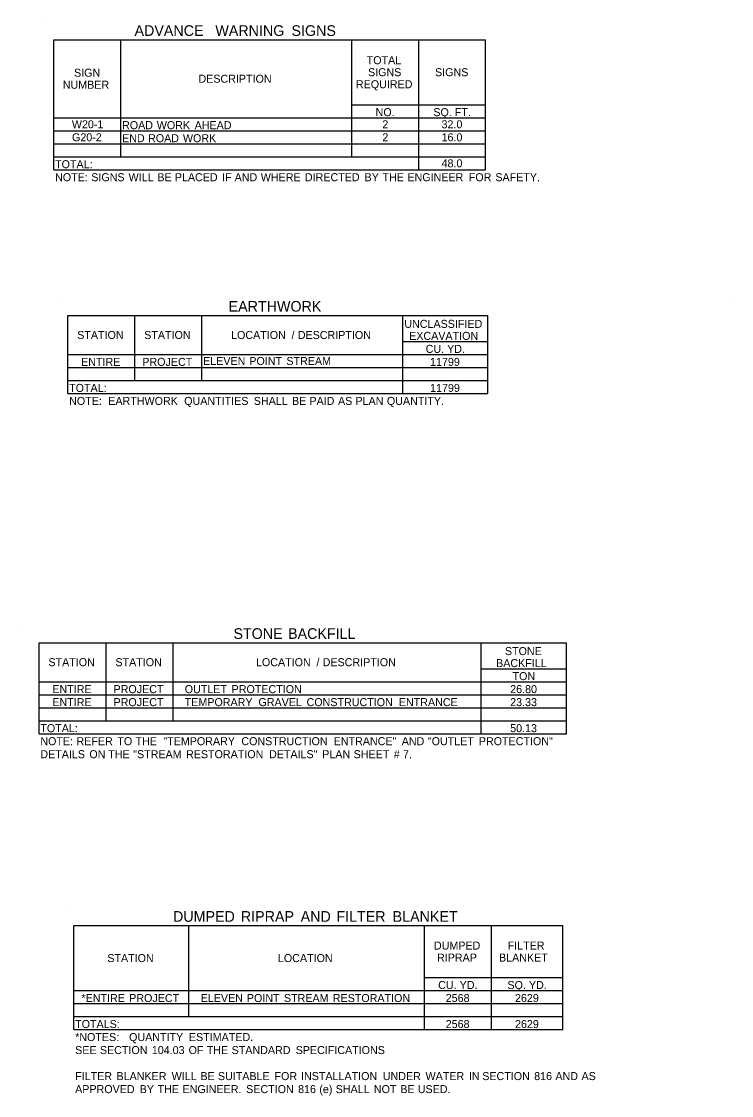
# Model space of a CAD drawing. Extents: x -2001791 to 62654501, y -2521700 to -592476.
# Drawn here: x -2001791 to -2001259, y -593387 to -592582 of the extents above; entities that cross this region are included whole.
import ezdxf

# ---------------------------------------------------------------- set-up
doc = ezdxf.new("R2010")
doc.units = 0
doc.layers.add('Default', color=7, linetype='Continuous')
doc.layers.add('R_Border', color=7, linetype='Continuous')

msp = doc.modelspace()

# ---------------------------------------------------------------- linework, layer by layer
at = {"layer": 'Default'}
for p, q in [((-2001767.25, -592596.02), (-2001443.55, -592596.02)), ((-2001767.25, -592693.52), (-2001767.25, -592596.02)), ((-2001767.25, -592693.52), (-2001767.25, -592596.02)), ((-2001717.04, -592683.77), (-2001717.04, -592596.02)), ((-2001543.98, -592683.77), (-2001543.98, -592596.02)), ((-2001493.76, -592644.77), (-2001493.76, -592596.02)), ((-2001493.76, -592693.52), (-2001493.76, -592596.02)), ((-2001443.55, -592693.52), (-2001443.55, -592596.02)), ((-2001443.55, -592693.52), (-2001443.55, -592596.02)), ((-2001543.98, -592644.77), (-2001443.55, -592644.77)), ((-2001767.25, -592654.52), (-2001443.55, -592654.52)), ((-2001717.04, -592683.77), (-2001717.04, -592654.52)), ((-2001543.98, -592683.77), (-2001543.98, -592654.52)), ((-2001493.76, -592693.52), (-2001493.76, -592654.52)), ((-2001767.25, -592664.27), (-2001443.55, -592664.27)), ((-2001767.25, -592674.02), (-2001443.55, -592674.02)), ((-2001543.98, -592674.02), (-2001443.55, -592674.02)), ((-2001767.25, -592683.77), (-2001543.98, -592683.77)), ((-2001767.25, -592683.77), (-2001443.55, -592683.77)), ((-2001767.25, -592693.52), (-2001443.55, -592693.52)), ((-2001756.73, -592802.65), (-2001441.81, -592802.65)), ((-2001756.73, -592861.15), (-2001756.73, -592802.65)), ((-2001756.73, -592861.15), (-2001756.73, -592802.65)), ((-2001706.52, -592851.4), (-2001706.52, -592802.65)), ((-2001656.31, -592851.4), (-2001656.31, -592802.65)), ((-2001505.67, -592861.15), (-2001505.67, -592802.65)), ((-2001441.81, -592822.15), (-2001441.81, -592802.65)), ((-2001441.81, -592861.15), (-2001441.81, -592802.65)), ((-2001505.67, -592822.15), (-2001441.81, -592822.15)), ((-2001441.81, -592831.9), (-2001441.81, -592822.15)), ((-2001756.73, -592831.9), (-2001441.81, -592831.9)), ((-2001756.73, -592831.9), (-2001441.81, -592831.9)), ((-2001706.52, -592851.4), (-2001706.52, -592831.9)), ((-2001656.31, -592851.4), (-2001656.31, -592831.9)), ((-2001505.67, -592851.4), (-2001505.67, -592831.9)), ((-2001441.81, -592861.15), (-2001441.81, -592831.9)), ((-2001756.73, -592841.65), (-2001441.81, -592841.65)), ((-2001756.73, -592851.4), (-2001706.52, -592851.4)), ((-2001756.73, -592851.4), (-2001441.81, -592851.4)), ((-2001756.73, -592861.15), (-2001441.81, -592861.15)), ((-2001778.31, -593047.86), (-2001382.94, -593047.86)), ((-2001778.31, -593116.11), (-2001778.31, -593047.86)), ((-2001778.31, -593116.11), (-2001778.31, -593047.86)), ((-2001728.09, -593106.36), (-2001728.09, -593047.86)), ((-2001677.88, -593106.36), (-2001677.88, -593047.86)), ((-2001446.81, -593116.11), (-2001446.81, -593047.86)), ((-2001382.94, -593116.11), (-2001382.94, -593047.86)), ((-2001382.94, -593116.11), (-2001382.94, -593047.86)), ((-2001446.81, -593067.36), (-2001382.94, -593067.36)), ((-2001778.31, -593077.11), (-2001382.94, -593077.11)), ((-2001728.09, -593106.36), (-2001728.09, -593077.11)), ((-2001677.88, -593106.36), (-2001677.88, -593077.11)), ((-2001446.81, -593106.36), (-2001446.81, -593077.11)), ((-2001778.31, -593086.86), (-2001382.94, -593086.86)), ((-2001728.09, -593086.86), (-2001677.88, -593086.86)), ((-2001778.31, -593096.61), (-2001382.94, -593096.61)), ((-2001778.31, -593106.36), (-2001382.94, -593106.36)), ((-2001778.31, -593106.36), (-2001382.94, -593106.36)), ((-2001778.31, -593116.11), (-2001382.94, -593116.11)), ((-2001752.22, -593259.83), (-2001385.62, -593259.83)), ((-2001752.22, -593337.83), (-2001752.22, -593259.83)), ((-2001752.22, -593337.83), (-2001752.22, -593259.83)), ((-2001665.93, -593328.08), (-2001665.93, -593259.83)), ((-2001489.46, -593337.83), (-2001489.46, -593259.83)), ((-2001439.24, -593337.83), (-2001439.24, -593259.83)), ((-2001385.62, -593337.83), (-2001385.62, -593259.83)), ((-2001385.62, -593337.83), (-2001385.62, -593259.83)), ((-2001489.46, -593298.83), (-2001385.62, -593298.83)), ((-2001752.22, -593308.58), (-2001385.62, -593308.58)), ((-2001752.22, -593308.58), (-2001385.62, -593308.58)), ((-2001665.93, -593328.08), (-2001665.93, -593308.58)), ((-2001489.46, -593337.83), (-2001489.46, -593308.58)), ((-2001752.22, -593318.33), (-2001385.62, -593318.33)), ((-2001752.22, -593328.08), (-2001665.93, -593328.08)), ((-2001752.22, -593328.08), (-2001385.62, -593328.08)), ((-2001752.22, -593337.83), (-2001385.62, -593337.83))]:
    msp.add_line(p, q, dxfattribs=at)
at = {"layer": 'R_Border'}
for p, q in [((-2001773.1, -592582.37), (-2001773.1, -592582.37)), ((-2001762.58, -592789), (-2001762.58, -592789)), ((-2001259.27, -592788.65), (-2001259.27, -592788.65)), ((-2001791.47, -593034.21), (-2001791.47, -593034.21)), ((-2001758.07, -593246.18), (-2001758.07, -593246.18))]:
    msp.add_line(p, q, dxfattribs=at)

# ---------------------------------------------------------------- texts
at = {"layer": 'Default'}
for s, height, p in [('                      ADVANCE', 8, (-2001772.13, -592593.2)), (' WARNING', 8, (-2001649.12, -592593.2)), (' SIGNS', 8, (-2001592.05, -592593.2)), ('TOTAL', 6, (-2001532.71, -592614.4)), ('SIGN', 6, (-2001752.06, -592623.77)), ('SIGNS', 6, (-2001531.71, -592623.4)), ('SIGNS', 6, (-2001481.5, -592623.4)), ('NUMBER', 6, (-2001760.52, -592632.77)), ('DESCRIPTION', 6, (-2001658.82, -592628.27)), ('REQUIRED', 6, (-2001540.79, -592632.4)), ('NO.', 6, (-2001526.03, -592653.32)), ('SQ.', 6, (-2001482.75, -592653.32)), (' FT.', 6, (-2001468.89, -592653.32)), ('W20-1', 6, (-2001753.71, -592662.4)), ('ROAD', 6, (-2001716.06, -592663.07)), (' WORK', 6, (-2001692.29, -592663.07)), (' AHEAD', 6, (-2001663.9, -592663.07)), ('2', 6, (-2001520.98, -592662.4)), ('32.0', 6, (-2001476.61, -592662.4)), ('G20-2', 6, (-2001753.57, -592672.15)), ('END', 6, (-2001716.06, -592672.82)), (' ROAD', 6, (-2001698.81, -592672.82)), (' WORK', 6, (-2001672.7, -592672.82)), ('2', 6, (-2001520.98, -592672.15)), ('16.0', 6, (-2001476.61, -592672.15)), ('48.0', 6, (-2001476.6, -592691.65)), ('TOTAL:', 6, (-2001766.28, -592692.32)), ('NOTE:', 6, (-2001766.28, -592702.07)), (' SIGNS', 6, (-2001741.39, -592702.07)), (' WILL', 6, (-2001713.41, -592702.07)), (' BE', 6, (-2001691.82, -592702.07)), (' PLACED', 6, (-2001678.75, -592702.07)), (' IF', 6, (-2001643.33, -592702.07)), (' AND', 6, (-2001633.93, -592702.07)), (' WHERE', 6, (-2001614.35, -592702.07)), (' DIRECTED', 6, (-2001581.26, -592702.07)), (' BY', 6, (-2001536.53, -592702.07)), (' THE', 6, (-2001523.08, -592702.07)), (' ENGINEER', 6, (-2001504.43, -592702.07)), (' FOR', 6, (-2001458.42, -592702.07)), (' SAFETY.', 6, (-2001438.51, -592702.07)), ('STONE', 8, (-2001632.59, -593045.03)), (' BACKFILL', 8, (-2001594.63, -593045.03)), ('STONE', 6, (-2001429.11, -593057.16)), ('STATION', 6, (-2001771.26, -593065.48)), ('STATION', 6, (-2001721.05, -593065.48)), ('LOCATION', 6, (-2001615.71, -593065.48)), (' /', 6, (-2001572.6, -593065.48)), (' DESCRIPTION', 6, (-2001567.94, -593065.48)), ('BACKFILL', 6, (-2001435.71, -593066.16)), ('TON', 6, (-2001423.39, -593075.91)), ('ENTIRE', 6, (-2001768.35, -593085.66)), ('PROJECT', 6, (-2001722.47, -593085.66)), ('OUTLET', 6, (-2001669.11, -593085.66)), (' PROTECTION', 6, (-2001636.2, -593085.66)), ('26.80', 6, (-2001425.16, -593085.66)), ('ENTIRE', 6, (-2001768.35, -593095.41)), ('PROJECT', 6, (-2001722.47, -593095.41)), ('TEMPORARY', 6, (-2001669.11, -593095.41)), (' GRAVEL', 6, (-2001616.06, -593095.41)), (' CONSTRUCTION', 6, (-2001580.02, -593095.41)), (' ENTRANCE', 6, (-2001510.84, -593095.41)), ('23.33', 6, (-2001425.17, -593095.41)), ('TOTAL:', 6, (-2001777.33, -593114.91)), ('50.13', 6, (-2001425.18, -593114.91)), ('NOTE:', 6, (-2001777.33, -593124.66)), (' REFER', 6, (-2001752.45, -593124.66)), (' TO', 6, (-2001721.81, -593124.66)), (' THE', 6, (-2001708.22, -593124.66)), ('  "TEMPORARY', 6, (-2001689.57, -593124.66)), (' CONSTRUCTION', 6, (-2001628.89, -593124.66)), (' ENTRANCE"', 6, (-2001559.71, -593124.66)), (' AND', 6, (-2001508.68, -593124.66)), (' "OUTLET', 6, (-2001489.1, -593124.66)), (' PROTECTION"', 6, (-2001450.89, -593124.66)), ('DETAILS', 6, (-2001777.33, -593134.41)), (' ON', 6, (-2001742.83, -593134.41)), (' "STREAM', 6, (-2001709.96, -593134.41)), (' RESTORATION', 6, (-2001670.35, -593134.41)), (' DETAILS"', 6, (-2001608.15, -593134.41)), (' SHEET', 6, (-2001544.75, -593134.41)), (' THE', 6, (-2001728.61, -593134.41)), (' PLAN', 6, (-2001568.29, -593134.41)), (' #', 6, (-2001514.64, -593134.41)), (' 7.', 6, (-2001507.75, -593134.41)), ('DUMPED', 8, (-2001677.89, -593257)), (' RIPRAP', 8, (-2001630, -593257)), (' AND', 8, (-2001585.17, -593257)), (' FILTER', 8, (-2001558.4, -593257)), (' BLANKET', 8, (-2001516.23, -593257)), ('DUMPED', 6, (-2001482.31, -593277.83)), ('FILTER', 6, (-2001427.08, -593277.83)), ('STATION', 6, (-2001727.14, -593287.2)), ('LOCATION', 6, (-2001599.25, -593287.2)), ('RIPRAP', 6, (-2001480, -593286.83)), ('BLANKET', 6, (-2001433.54, -593286.83)), ('CU.', 6, (-2001479.14, -593307.38)), (' YD.', 6, (-2001465.28, -593307.38)), ('SQ.', 6, (-2001427.23, -593307.38)), (' YD.', 6, (-2001413.36, -593307.38)), ('*ENTIRE', 6, (-2001746.5, -593317.13)), (' PROJECT', 6, (-2001712.94, -593317.13)), ('ELEVEN', 6, (-2001657.16, -593317.13)), (' POINT', 6, (-2001624.75, -593317.13)), (' STREAM', 6, (-2001596.98, -593317.13)), (' RESTORATION', 6, (-2001560.34, -593317.13)), ('2568', 6, (-2001473.48, -593317.13)), ('2629', 6, (-2001421.57, -593317.13)), ('TOTALS:', 6, (-2001751.24, -593336.63)), ('2568', 6, (-2001473.48, -593336.63)), ('2629', 6, (-2001421.56, -593336.63)), ('*NOTES:', 6, (-2001751.24, -593346.38)), ('   QUANTITY', 6, (-2001717.5, -593346.38)), (' ESTIMATED.', 6, (-2001668.19, -593346.38)), ('SEE', 6, (-2001751.24, -593356.13)), (' SECTION', 6, (-2001734.91, -593356.13)), (' 104.03', 6, (-2001696, -593356.13)), (' OF', 6, (-2001668.43, -593356.13)), (' THE', 6, (-2001654.84, -593356.13)), (' STANDARD', 6, (-2001636.19, -593356.13)), (' SPECIFICATIONS', 6, (-2001588.19, -593356.13)), ('FILTER', 6, (-2001751.24, -593375.63)), (' BLANKER', 6, (-2001722.48, -593375.63)), (' WILL', 6, (-2001681.12, -593375.63)), (' BE', 6, (-2001659.53, -593375.63)), (' SUITABLE', 6, (-2001646.47, -593375.63)), (' FOR', 6, (-2001604.05, -593375.63)), (' INSTALLATION', 6, (-2001584.14, -593375.63)), (' UNDER', 6, (-2001522.87, -593375.63)), (' WATER', 6, (-2001490.84, -593375.63)), (' IN', 6, (-2001458.35, -593375.63)), (' SECTION', 6, (-2001448.33, -593375.63)), (' 816', 6, (-2001409.42, -593375.63)), (' AND', 6, (-2001393.49, -593375.63)), (' AS', 6, (-2001373.91, -593375.63)), ('APPROVED', 6, (-2001751.24, -593385.38)), (' BY', 6, (-2001705.1, -593385.38)), (' THE', 6, (-2001691.65, -593385.38)), (' ENGINEER.', 6, (-2001673, -593385.38)), (' SECTION', 6, (-2001625.28, -593385.38)), (' 816', 6, (-2001586.37, -593385.38)), (' (e)', 6, (-2001570.44, -593385.38)), (' SHALL', 6, (-2001558.18, -593385.38)), (' NOT', 6, (-2001529.59, -593385.38)), (' BE', 6, (-2001509.73, -593385.38)), (' USED.', 6, (-2001496.66, -593385.38))]:
    msp.add_text(s, height=height, dxfattribs=at).set_placement(p)
for s, height, p in [('EARTHWORK', 8, (-2001636.21, -592799.83)), ('UNCLASSIFIED', 6, (-2001504.51, -592811.95)), ('STATION', 6, (-2001749.69, -592820.28)), ('STATION', 6, (-2001699.48, -592820.28)), ('LOCATION', 6, (-2001634.35, -592820.28)), (' /', 6, (-2001591.24, -592820.28)), (' DESCRIPTION', 6, (-2001586.58, -592820.28)), ('EXCAVATION', 6, (-2001500.89, -592820.95)), ('CU.', 6, (-2001488.53, -592830.7)), (' YD.', 6, (-2001474.67, -592830.7)), ('ENTIRE', 6, (-2001746.78, -592840.45)), ('PROJECT', 6, (-2001700.9, -592840.45)), ('ELEVEN', 6, (-2001655.33, -592839.78)), (' POINT', 6, (-2001622.93, -592839.78)), (' STREAM', 6, (-2001595.15, -592839.78)), ('11799', 6, (-2001485.2, -592840.45)), ('TOTAL:', 6, (-2001755.76, -592859.95)), ('11799', 6, (-2001485.2, -592859.95)), ('NOTE:', 6, (-2001755.76, -592869.7)), ('  EARTHWORK', 6, (-2001730.87, -592869.7)), (' QUANTITIES', 6, (-2001671.74, -592869.7)), (' SHALL', 6, (-2001619.54, -592869.7)), (' BE', 6, (-2001590.95, -592869.7)), (' PAID', 6, (-2001577.88, -592869.7)), (' AS', 6, (-2001556.43, -592869.7)), (' PLAN', 6, (-2001543.36, -592869.7)), (' QUANTITY.', 6, (-2001519.81, -592869.7))]:
    msp.add_text(s, height=height, rotation=360, dxfattribs=at).set_placement(p)

doc.saveas('drawing.dxf')
